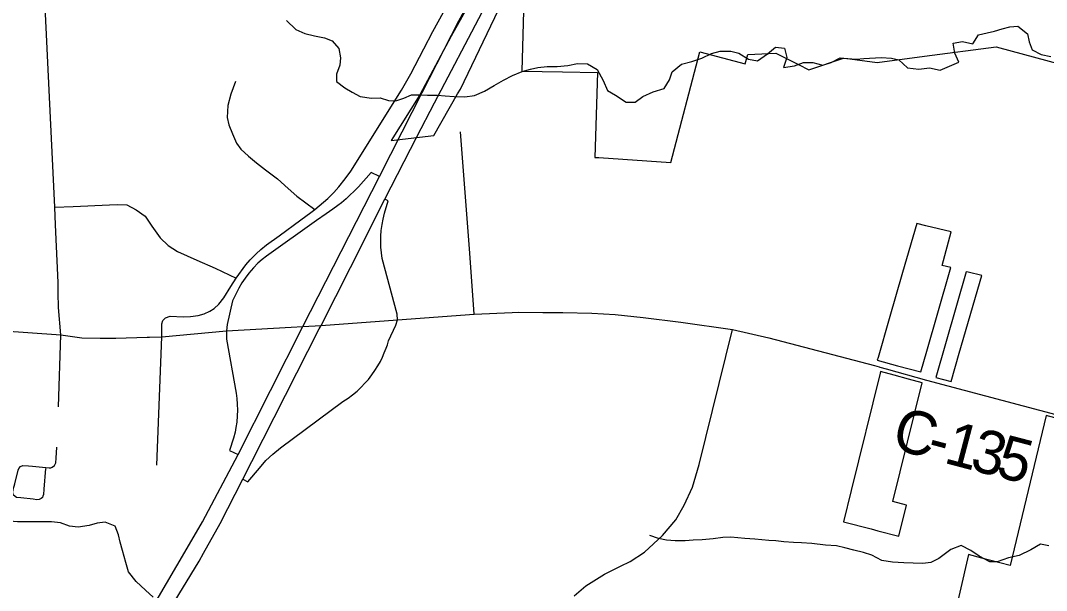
# Model space of a CAD drawing. Extents: x 114843 to 284848, y 317643 to 566895.
# Drawn here: x 190209 to 197293, y 354619 to 358558 of the extents above; entities that cross this region are included whole.
import ezdxf

# ---------------------------------------------------------------- set-up
doc = ezdxf.new("R2010")
doc.units = 0
for name, color, linetype in [('GM_X_City_Street', 7, 'Continuous'), ('GM_X_Corporation', 7, 'Continuous'), ('GM_X_County_Road', 7, 'Continuous'), ('GM_X_County_Road_Text', 7, 'Continuous'), ('GM_X_Interchange_Ramps', 7, 'Continuous'), ('GM_X_Interstate_Route', 7, 'Continuous'), ('GM_X_Minor_River', 7, 'Continuous')]:
    doc.layers.add(name, color=color, linetype=linetype)

msp = doc.modelspace()

# ---------------------------------------------------------------- linework, layer by layer
at = {"layer": 'GM_X_City_Street'}
for p, q in [((190471.4, 355887.2), (190487.1, 356384.7)), ((191149.8, 355484.9), (191185.1, 356372.3))]:
    msp.add_line(p, q, dxfattribs=at)
for points in [[(190445.8, 357267.2), (190408.2, 358027.5), (190378.4, 358652.1), (190373.2, 358748.2), (190370.5, 358808.6), (190360.2, 358897.3), (190347.9, 358951.6), (190338.6, 358994.1), (190321.1, 359046.1), (190266.2, 359189.8), (190133, 359418.1)], [(191693.3, 358136.5), (191661.2, 358048.2), (191641.1, 357969.9), (191635.1, 357887.7), (191647.1, 357837.5), (191673.1, 357775.3), (191701.2, 357711.1), (191729.2, 357668.9), (191783.3, 357620.8), (191837.5, 357574.6), (191899.6, 357526.5), (191983.8, 357464.2), (192056, 357398), (192116.1, 357343.8), (192242.1, 357252.3)], [(193340.9, 356527.9), (193310.5, 356950.3), (193246.4, 357788.1)], [(190445.8, 357267.2), (190572.5, 357273.3), (190823, 357284.8), (190876.6, 357287.4), (190942.7, 357284.2), (191007.9, 357250.3), (191069.4, 357204.9), (191115.7, 357136.4), (191173.6, 357056.5), (191227.5, 357003.3), (191292.8, 356961.7), (191425.2, 356902.1), (191552.9, 356846), (191696.7, 356776.9)], [(190487.1, 356384.7), (190470.9, 356575.4), (190467.9, 356676), (190468.9, 356748.4), (190451.1, 357144.9), (190445.8, 357267.2)], [(194031.5, 354582.1), (194111.6, 354652.1), (194241.2, 354732.4), (194351.2, 354787.7), (194419.1, 354820.4), (194517.8, 354884.4), (194642.9, 354998.4), (194734.5, 355106.6), (194792, 355209.9), (194849.4, 355334.3), (194895.4, 355489.6), (195125.5, 356422)], [(190292.6, 355477.4), (190406.8, 355467), (190418.6, 355467.1), (190426.3, 355471.9), (190443.3, 355482.5), (190447.9, 355492.2), (190452.6, 355501.8), (190455.2, 355533.7), (190459.6, 355610.2)], [(190210, 355259.5), (190181, 355262.9), (190160.9, 355277.6), (190154.7, 355296.5), (190157.9, 355316.2), (190168.4, 355357.1), (190192.4, 355451.2), (190198, 355461.4), (190209.3, 355475.8), (190223.7, 355483.1), (190264.1, 355480), (190292.6, 355477.4)], [(190381.1, 355461.1), (190370, 355319), (190366.9, 355281.6), (190363.2, 355271.9), (190359.6, 355262.1), (190351.3, 355255.6), (190343.2, 355249.2), (190337.1, 355248.4), (190322.4, 355246.6), (190296.9, 355249.5), (190210, 355259.5)]]:
    msp.add_lwpolyline(points, dxfattribs=at)
at = {"layer": 'GM_X_Corporation'}
for points in [[(193517.9, 359051.8), (193182.1, 358449.2), (192965.6, 358044.8), (192767.5, 357728.6), (193062.6, 357762.4), (193226.8, 358050.2), (193246.2, 358084.1), (193508.2, 358632.3)], [(193682, 358624), (193670.3, 358207.9), (193952.3, 358204.1), (194194.1, 358198.1), (194173.5, 357612), (194202.6, 357610), (194698.2, 357576.5), (194900.2, 358340.9), (195212, 358257.5), (195231, 358323.4), (195424.3, 358331.7), (195580.8, 358253.4), (195652.9, 358217.2), (195891.7, 358298.6), (195935.9, 358292.9), (196123.7, 358268.7), (196451.8, 358311.8), (196945.1, 358376.5), (197566.3, 358208.4)], [(197495.5, 355772.7), (197290.5, 355827.3), (197042.6, 354791.7), (196899.7, 354829.6), (196847.4, 354843.5), (196755.6, 354867.9), (196627.2, 354318.4)]]:
    msp.add_lwpolyline(points, dxfattribs=at)
for points in [[(196265.3, 356172.5), (196425.7, 356129.9), (196466.5, 356272.7), (196624.2, 356818.6), (196633.3, 356850), (196573, 356865.4), (196636.1, 357096.9), (196460.3, 357140), (196398.1, 357155.4), (196299.4, 356816.2), (196207.3, 356495.8), (196130.6, 356228.9), (196124.8, 356209.8)], [(196737.7, 356822.2), (196529.1, 356091.3), (196634.6, 356063.3), (196691.3, 356259.8), (196846.1, 356796.6), (196752.9, 356819.5)], [(196240.8, 356106.5), (196147.4, 356131.4), (196144.6, 356121.3), (195944.3, 355309.2), (195891.4, 355094.6), (196082.5, 355044.4), (196128.3, 355032.3), (196273.1, 354994.5), (196326.6, 355208.5), (196232.4, 355233.4), (196435.5, 356054.7), (196340.4, 356080)]]:
    msp.add_lwpolyline(points, close=True, dxfattribs=at)
at = {"layer": 'GM_X_County_Road'}
for points in [[(191185.1, 356372.3), (191184.4, 356461.8), (191191.1, 356485.9), (191209.9, 356504.1), (191241.7, 356513.8), (191332.9, 356510.2), (191382.8, 356511.4), (191434.4, 356518.7), (191476.5, 356530.1), (191515.1, 356548.5), (191545.9, 356567.6), (191579.2, 356597.1), (191611.6, 356640.4), (191660.9, 356719.9), (191696.7, 356776.9), (191764.8, 356868.6), (191794.7, 356904.9), (191834.8, 356946.5), (191867.3, 356975.2), (191906.6, 357008.2), (191994.8, 357070.7), (192145.4, 357181.1), (192213.9, 357230.6), (192242.1, 357252.3), (192330.2, 357327.8), (192372.1, 357369.4), (192407, 357409.2), (192450.5, 357463.8), (192489.7, 357517.4), (192839.3, 358076.5), (192903, 358188.8), (192992.9, 358362.4), (193055.8, 358480.8), (193290.1, 358909.2)], [(192811.1, 356488.4), (193340.9, 356527.9), (193602.6, 356540.4)], [(193602.6, 356540.4), (193644.4, 356542.4), (193815, 356540.1), (193954.3, 356539.5), (194154.6, 356535.9), (194314.5, 356526.8), (194507.2, 356505.6), (194768.7, 356472.7), (195125.5, 356422), (195375.8, 356364.4), (196104.6, 356174), (196137.1, 356165)], [(191083.6, 356369.9), (191098.4, 356370.4), (191185.1, 356372.3), (191631.4, 356413.1), (192076.7, 356438.6), (192159.2, 356443.4), (192284, 356450.5), (192811.1, 356488.4)], [(190060.7, 356416.6), (190487.1, 356384.7), (190633, 356366.2), (190757.8, 356362), (190867, 356361.9), (191083.6, 356369.9)], [(196137.1, 356165), (196142.5, 356163.5), (196187.2, 356151)], [(196187.2, 356151), (196465.5, 356073), (197393, 355827)]]:
    msp.add_lwpolyline(points, dxfattribs=at)
at = {"layer": 'GM_X_Interchange_Ramps'}
for points in [[(192687.8, 357479.2), (192630.7, 357508.4), (192541.8, 357408.7), (192514.5, 357380.2), (192481.5, 357348.2), (192457.4, 357326.4), (192424.6, 357298.7), (192399.4, 357278.8), (192365.9, 357254), (192318.3, 357222.1), (192252.8, 357175.6)], [(192697.1, 357054.1), (192697.3, 357067.3), (192700.2, 357107.8), (192705.1, 357147.3), (192711.8, 357185.5), (192721.1, 357226), (192746.3, 357312.6), (192724.3, 357323.9)], [(192252.8, 357175.6), (191906.6, 356929.9), (191877.6, 356906.8), (191847.8, 356880.1), (191816.6, 356848.5), (191785, 356811.8), (191759.3, 356777.4), (191738, 356745.2), (191716.6, 356708), (191698.4, 356671.2), (191673.1, 356621.6), (191636.3, 356457.8), (191631.4, 356413.1)], [(192811.1, 356488.4), (192809.7, 356528.7), (192706, 356913.4), (192701, 356951.4), (192697.8, 356990.8), (192696.6, 357027.6), (192697.1, 357054.1)], [(192708.1, 356232.1), (192720.2, 356260.4), (192733.7, 356293.6), (192742.6, 356317.7), (192750.2, 356345), (192801.1, 356451.8), (192811.1, 356488.4)], [(191631.4, 356413.1), (191630.1, 356356.2), (191696.8, 355982.7), (191702, 355946.6), (191705.6, 355905.6), (191706.8, 355864.9), (191705.7, 355825.9), (191702, 355782.9), (191696.6, 355745.8), (191690.1, 355712.5), (191679.5, 355671.1), (191652.7, 355586.6), (191711.3, 355559.7)], [(191744.4, 355389.6), (191777.7, 355369.1), (191859.3, 355465), (191903.1, 355516.9), (191950.2, 355560.4), (192003, 355605.6), (192434.2, 355926), (192470.3, 355949.1), (192501.3, 355971.7), (192532.8, 355997.4), (192559.8, 356022.2), (192589.7, 356053), (192611.6, 356078.1), (192635.8, 356109.1), (192656.5, 356138.9), (192676.2, 356170.6), (192693.4, 356201.9), (192708.1, 356232.1)]]:
    msp.add_lwpolyline(points, dxfattribs=at)
at = {"layer": 'GM_X_Interstate_Route'}
for points in [[(192843.8, 357788.3), (192981.6, 358061.4), (193235.9, 358555.4), (193394, 358845.8), (193558.4, 359131.8), (193708.2, 359383.9), (193839.8, 359596.6), (194054.5, 359932.5), (194260.4, 360236.3), (194537.3, 360624.3), (194712.2, 360857.2), (194903, 361107.7)], [(192946.1, 357754.3), (193066.8, 357988.5), (193396.7, 358614.7), (193645.4, 359067), (193928.7, 359537.3), (194349.3, 360177), (194633.1, 360567.2), (194797.6, 360793.3), (194892.9, 360918.4)], [(191359.2, 354912.4), (191464.8, 355094.1), (191711.3, 355559.7), (192159.2, 356443.4), (192687.8, 357479.2), (192843.8, 357788.3)], [(192486.3, 356851.8), (192724.3, 357323.9), (192946.1, 357754.3)], [(192272, 356426.9), (192284, 356450.5), (192486.3, 356851.8)], [(191472.4, 354877.2), (191586.4, 355081.9), (191744.4, 355389.6), (191805.8, 355511.4), (192272, 356426.9)], [(190054.5, 353063.9), (190230.9, 353266), (190481.5, 353580.8), (190725.6, 353912.1), (190880.7, 354138), (191145.5, 354544.6), (191359.2, 354912.4)], [(190163.8, 353028.4), (190329.8, 353218.7), (190580.4, 353533.4), (190824.5, 353864.7), (191006.6, 354131.3), (191244.3, 354497.3), (191441.3, 354821.4), (191472.4, 354877.2)]]:
    msp.add_lwpolyline(points, dxfattribs=at)
at = {"layer": 'GM_X_Minor_River'}
for points in [[(192046.5, 358558.4), (192110.1, 358495.8), (192171.9, 358467.4), (192237.9, 358450.9), (192307.8, 358438.5), (192361.7, 358418.1), (192407.4, 358363.7), (192419, 358299.4), (192412.7, 358249.4), (192390.3, 358187.4), (192389.9, 358137.3), (192447.7, 358092.8), (192499.5, 358062.4), (192553.4, 358032), (192633.3, 358021.5), (192691.4, 358023.1), (192749.3, 358004.7), (192801.3, 358002.3), (192855.4, 358020), (192909.6, 358043.7), (192963.6, 358043.4), (193019.6, 358041), (193087.7, 358042.6), (193141.7, 358036.3), (193203.7, 358031.8), (193277.7, 358031.4), (193343.8, 358039), (193412, 358068.6), (193480.3, 358108.3), (193544.6, 358145.9), (193606.8, 358177.6), (193673, 358205.3), (193731.1, 358220.9)], [(193731.1, 358220.9), (193781.2, 358232.6), (193845.3, 358240.2), (193913.3, 358239.8), (193987.4, 358247.4), (194055.5, 358261), (194123.6, 358258.5), (194191.3, 358220), (194232.9, 358143.6), (194262.5, 358075.2), (194316.3, 358040.8), (194390, 357994.2), (194454, 357993.8), (194506.3, 358033.6), (194576.6, 358065.2), (194652.7, 358088.8), (194689.1, 358148.7), (194709.5, 358202.7), (194771.9, 358256.4), (194844, 358274), (194914.2, 358297.6), (194980.4, 358329.2), (195040.6, 358346.9), (195114.6, 358346.4), (195168.6, 358332), (195236.3, 358291.5), (195298.3, 358279.1), (195366.6, 358326.8), (195421, 358374.5), (195484.9, 358366.1), (195500.5, 358301.9), (195478.1, 358233.9), (195554.2, 358243.4), (195614.4, 358267.1), (195680.4, 358266.7), (195748.3, 358248.2), (195806.5, 358267.9), (195868.7, 358299.5), (195920.7, 358295.2), (195978.7, 358290.8), (196032.7, 358294.5), (196152.9, 358301.8), (196222.9, 358297.3), (196274.8, 358287), (196334.5, 358230.5), (196412.5, 358221.9), (196484.6, 358231.5), (196558.5, 358215), (196624.7, 358242.6), (196688.9, 358270.3), (196661.3, 358332.6), (196649.7, 358400.8), (196713.8, 358412.5), (196785.8, 358396), (196824.2, 358457.9), (196884.3, 358473.5), (196934.4, 358483.2), (196986.5, 358500.9), (197040.7, 358514.6), (197094.7, 358518.3), (197162.4, 358465.7), (197174.1, 358411.5), (197193.7, 358355.3), (197257.5, 358322.8), (197323.5, 358308.4)], [(191125.5, 354572.7), (191071.5, 354620.8), (191007.6, 354681), (190953.6, 354749.3), (190935.7, 354813.4), (190913.8, 354895.6), (190895.9, 354953.7), (190886, 355003.9), (190862, 355064), (190794, 355092.2), (190738, 355084.2), (190681.9, 355068.3), (190605.9, 355056.4), (190547.8, 355064.5), (190485.8, 355086.6), (190421.8, 355092.7), (190187.6, 355093), (190105.6, 355101.2), (189966.1, 355212.3)], [(197310.3, 354927), (197252.2, 354939.1), (197186.1, 354901.1), (197104, 354861.1), (197029.9, 354845.2), (196953.8, 354817.2), (196901.8, 354817.3), (196827.8, 354857.5), (196771.8, 354895.6), (196703.8, 354929.8), (196633.7, 354901.8), (196549.6, 354839.8), (196495.5, 354813.8), (196439.5, 354805.9), (196373.4, 354808), (196309.4, 354810.1), (196229.3, 354814.2), (196155.3, 354826.3), (196087.3, 354862.5), (196029.3, 354882.6), (195963.3, 354898.7), (195901.3, 354914.8), (195843.2, 354926.9), (195767.2, 354933), (195673.1, 354943.2), (195601.1, 354949.3), (195547.1, 354951.4), (195479, 354955.5), (195425, 354961.6), (195375, 354963.6), (195278.9, 354973.8), (195210.9, 354977.9), (195114.8, 354988), (195058.8, 354986.1), (194990.7, 354976.2), (194914.7, 354970.3), (194854.6, 354966.3), (194798.6, 354962.4), (194728.5, 354962.5), (194670.5, 354966.6), (194614.5, 354978.7), (194554.5, 354998.8)]]:
    msp.add_lwpolyline(points, dxfattribs=at)

# ---------------------------------------------------------------- texts
at = {"layer": 'GM_X_County_Road_Text'}
for s, rotation, p in [('C', 343.75208, (196211.8, 355606.9)), ('1', 345.24381, (196575.6, 355503.8)), ('3', 345.32747, (196754.8, 355456.6)), ('-', 345.01399, (196455.3, 355536)), ('5', 345.33728, (196933.7, 355409.8))]:
    msp.add_text(s, height=300, rotation=rotation, dxfattribs=at).set_placement(p)

doc.saveas('drawing.dxf')
